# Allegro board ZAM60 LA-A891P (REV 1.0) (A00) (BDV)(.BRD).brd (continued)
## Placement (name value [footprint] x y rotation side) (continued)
RV507  100K_0402_5%  [R_0402]  282.19 68.44 270 top
RV508  1M_0402_5%  [R_0402]  201.96 84.25 0 bottom
RV509  1M_0402_5%  [R_0402]  199.62 82.97 180 top
RV510  4.7K_0402_5%  [R_0402]  235.06 79.62 270 top
RV511  4.7K_0402_5%  [R_0402]  234.17 78.71 90 top
RV514  100K_0402_5%  [R_0402]  232.09 86.22 270 top
RV515  100K_0402_5%  [R_0402]  232.99 84.43 180 top
RV516  2.2K_0402_5%  [R_0402]  199.5 69.27 270 top
RV517  2.2K_0402_5%  [R_0402]  202.83 69.25 90 bottom
RV518  2.2K_0402_5%  [R_0402]  201.23 85.41 270 top
RV519  2.2K_0402_5%  [R_0402]  202.13 85.41 270 top
RV600  4.99K_0402_1%  [R_0402]  222.76 73.77 270 bottom
RV601  4.7K_0402_5%  [R_0402]  235.53 73.57 180 top
RV602  4.7K_0402_5%  [R_0402]  222.43 75.16 0 bottom
RV603  4.7K_0402_5%  [R_0402]  232.55 75.35 180 top
RV604  100K_0402_5%  [R_0402]  220.47 67.59 90 top
RV605  100K_0402_5%  [R_0402]  219.38 70.27 0 top
RV606  1M_0402_5%  [R_0402]  227.64 69.39 270 bottom
RV607  1M_0402_5%  [R_0402]  223.64 69.46 270 bottom
RV608  100K_0402_5%  [R_0402]  219.57 69.38 0 top
RV609  100K_0402_5%  [R_0402]  220.28 72.06 270 top
RV610  4.7K_0402_5%  [R_0402]  228.09 72.86 90 bottom
RV611  4.7K_0402_5%  [R_0402]  234.5 68.67 90 top
RV612  4.7K_0402_5%  [R_0402]  237.17 68.67 90 top
RV613  4.7K_0402_5%  [R_0402]  237.17 71.61 270 top
RV614  4.7K_0402_5%  [R_0402]  234.5 71.61 270 top
RV615  4.7K_0402_5%  [R_0402]  235.53 74.46 180 top
RV616  4.7K_0402_5%  [R_0402]  227.2 73.77 270 bottom
RV617  4.7K_0402_5%  [R_0402]  235.39 69.58 270 top
RV618  4.7K_0402_5%  [R_0402]  236.28 69.58 270 top
RV619  4.7K_0402_5%  [R_0402]  236.28 70.7 90 top
RV620  4.7K_0402_5%  [R_0402]  235.39 70.7 90 top
RZ5  100K_0402_5%  [R_0402]  150.92 84.61 90 top
RZ8  2.2K_0402_5%  [R_0402]  252.56 13.27 270 top
RZ9  2.2K_0402_5%  [R_0402]  253.51 13.27 270 top
RZ10  1M_0402_5%  [R_0402]  258.94 12.83 270 top
RZ14  100K_0402_5%  [R_0402]  241.59 34.72 0 top
RZ15  100K_0402_5%  [R_0402]  244.34 34.72 180 top
RZ16  100K_0402_5%  [R_0402]  146.86 83.98 90 top
RZ17  0_0402_5%  [R0402_0OHM]  184.34 68.17 90 bottom
RZ18  4.7K_0402_5%  [R_0402]  247.32 22 90 top
RZ19  4.7K_0402_5%  [R_0402]  246.43 22 90 top
RZ21  33_0402_5%  [R_0402]  271.35 37.25 180 top
RZ22  10K_0402_5%  [R_0402]  268.81 34.71 180 top
RZ24  10K_0402_5%  [R_0402]  272.35 24.69 270 top
RZ25  390_0402_5%  [R_0402]  271.26 16.31 270 top
RZ26  33_0402_5%  [R_0402]  187.64 76.22 90 top
RZ27  110_0402_1%  [R_0402]  275.88 19.04 270 top
RZ28  330_0402_5%  [R_0402]  270.3 16.31 270 top
RZ29  33_0402_5%  [R_0402]  189.54 76.22 90 top
RZ30  33_0402_5%  [R_0402]  188.59 76.22 90 top
RZ31  100K_0402_5%  [R_0402]  286.88 80.05 0 top
RZ32  150_0402_5%  [R_0402]  289.61 82.46 0 top
RZ33  110_0402_1%  [R_0402]  283.72 79.04 270 top
RZ34  110_0402_1%  [R_0402]  285.62 82.4 180 top
RZ35  33_0402_5%  [R_0402]  187.89 79.49 270 top
RZ37  100K_0402_5%  [R_0402]  242.96 72.05 180 top
RZ38  100K_0402_5%  [R_0402]  251.2 30.46 180 top
RZ39  10K_0402_5%  [R_0402]  242.57 63.74 180 top
RZ40  100K_0402_5%  [R_0402]  244.22 56.67 90 top
RZ41  0_0402_5%  [R_0402]  200.95 47.23 270 top
RZ42  0_0402_5%  [R0402_0OHM]  201.86 47.23 270 top
RZ43  0_0402_5%  [R0402_0OHM]  243.84 72.92 270 top
RZ44  0.01_1206_1%  [R_1206]  200.02 41.22 270 top
RZ46  0_0603_5%  [R_0603]  220.33 61.94 180 top
RZ47  0_0402_5%  [R0402_0OHM]  220.84 64.31 180 top
RZ51  0_0402_5%  [R0402_0OHM]  267.01 33.79 90 top
RZ56  0_0402_5%  [R_0402]  252.69 24.75 0 top
RZ57  0_0402_5%  [R0402_0OHM]  252.69 25.65 0 top
SW1  SS3-CMFTQR9_3P  [SW_SS3-CMFTQR9_3P]  297.13 6.17 180 bottom
SW3  SKRBAAE010_4P  [SW_SKRBAAE010_4P]  294.16 86 270 top
T8  PAD~D  [TPC12]  169.05 48.09 0 top
T9  PAD~D  [TPC12]  253.6 32.78 90 top
T10  PAD~D  [TPC12]  128.53 70.99 180 bottom
T11  PAD~D  [TPC12]  127.01 70.48 180 bottom
T12  PAD~D  [TPC12]  135.21 77.65 0 top
T13  PAD~D  [TPC12]  127.87 72.39 180 bottom
T14  PAD~D  [TPC12]  133.77 77.99 0 top
T15  PAD~D  [TPC12]  133.07 76.77 0 top
T16  PAD~D  [TPC12]  173.73 60.24 0 top
T21  PAD~D  [TPC12]  177.24 61.06 180 bottom
T22  PAD~D  [TPC12]  174.2 62.45 0 top
T27  PAD~D  [TPC12]  173.86 57.7 180 bottom
T28  PAD~D  [TPC12]  128.78 47.15 180 bottom
T29  PAD~D  [TPC12]  127.16 47.45 180 bottom
T30  PAD~D  [TPC12]  128.7 77.99 180 bottom
T31  PAD~D  [TPC12]  129.78 78.75 180 bottom
T33  PAD~D  [TPC12]  140.46 78.33 180 bottom
T34  PAD~D  [TPC12]  142.3 78.33 180 bottom
T35  PAD~D  [TPC12]  130.03 65.94 180 bottom
T74  PAD~D  [TPC12]  129.45 64.5 180 bottom
T75  PAD~D  [TPC12]  126.48 65.18 180 bottom
T76  PAD~D  [TPC12]  137.32 77.98 0 top
T77  PAD~D  [TPC12]  132.45 78.45 0 top
T88  PAD~D  [TPC12]  261.22 86.41 180 top
T89  PAD~D  [TPC12]  261.24 87.86 180 top
T96  PAD~D  [TPC12]  259.93 58.29 180 top
T97  PAD~D  [TPC12]  252.03 73.65 180 top
T98  PAD~D  [TPC12]  258.02 72.16 180 top
T99  PAD~D  [TPC12]  252.11 72.17 0 top
T108  PAD~D  [TPC12]  213.17 76.03 0 top
T109  PAD~D  [TPC12]  167.71 78.56 0 top
TL1  NS692417  [MHPC_NS692417_24P]  279.42 81.51 180 bottom
UA1  -  [ALC3235-CG_MQFN48_6X6]  36.31 15.37 90 top
UC1  BDW-ULT-DDR3L_BGA1168  [BDW-ULT-DDR3L_BGA_1168P-T]  170.78 73.51 0 bottom
UC2  -  [W25Q64FVSSIQ_SO8]  190.61 68.5 0 bottom
UC3  -  [W25Q32FVSSIQ_SO8]  194.42 51.54 180 bottom
UC4  -  [74AHC1G09GW_TSSOP5]  185.23 72.82 180 top
UC5  TC7SH08FU_SSOP5~D  [TC7SH08FU_SSOP5]  187.74 70.85 0 top
UC6  TC7SH08FU_SSOP5~D  [TC7SH08FU_SSOP5]  186.5 52.57 270 top
UC7  -  [74CBTLV3126BQ_DHVQFN14_2P5X3]  90.03 59.31 270 bottom
UC8  -  [74AUP1G07GW_TSSOP5]  140.37 82.38 0 top
UD1  -  [74AUP1G07GW_TSSOP5]  146.15 19.79 0 top
UE1  ECE5048-LZY_DQFN132_11X11~D  [ECE5048-LZY_DQFN132_11X11]  258.62 70.96 180 top
UE2  -  [MEC5085-LZY_DQFN132_11X11]  262.69 47.91 180 top
UI1  SY6288D10CAC_MSOP8  [G547I2P81U_MSOP8]  91.7 84.21 270 bottom
UI2  SY6288D10CAC_MSOP8  [G547I2P81U_MSOP8]  255.09 92.9 270 bottom
UI3  -  [TPS2544RTER_WQFN16_3X3]  286.76 40.41 0 top
UI4  -  [PI3USB3102ZLEX_TQFN32_6X3]  181.18 96.08 0 top
UI5  -  [NX3DV221GM_XQFN10U10_2X1P55]  243.11 85.05 0 bottom
UL1  WGI218LM-QQ89-B0_QFN48_6X6~D  [WGI217LM-QPN9-A2_QFN48_6X6]  253.65 87.99 270 top
UL2  TC7SH08FU_SSOP5~D  [TC7SH08FU_SSOP5]  261.23 83.75 270 top
UL3  APE8990GN3B_SON14_2X3  [TPS22966DPUR_SON14_2X3]  248.79 28.88 90 top
UL4  PI3L720ZHEX_TQFN42_9X3P5~D  [PI3L720ZHEX_TQFN42_9X3P5]  268.46 73.5 0 top
UN1  LNG3DMTR_LGA16_3X3~D  [LNG3DMTR_LGA16_3X3]  279.73 8.26 270 bottom
UN2  -  [PI3EQX6741STZDEX_TQFN20_4X4]  265.04 19.67 180 top
UN3  TPS22967DSGR_SON8_2X2~D  [TPS22965DSGR_SON8_2X2]  249.91 18.45 270 top
UR1  OZ777FJ2LN-B1_QFN48_6X6  [OZ777FJ2LN_QFN48_6X6]  281.67 33.11 270 top
UV2  -  [AP2330W-7_SC59-3]  229.47 97.56 90 bottom
UV7  -  [PS8339BQFN56GTR2-A0_QFN56_7X7]  229.22 85.75 180 top
UV8  VMM3320BJGR_BGA168  [VMM3320BJGR_BGA_168P-NH]  203.01 72.64 90 top
UV9  W25X10CVSNIG_SO8  [W25X10BVSNIG_SO8]  200.83 74.52 270 bottom
UV10  APE8990GN3B_SON14_2X3  [TPS22966DPUR_SON14_2X3]  216.95 74.35 90 bottom
UV11  PI3C3125LEX_TSSOP14~D  [PI3C3125LEX_TSSOP14]  204.54 84.01 90 bottom
UV12  PI3C3125LEX_TSSOP14~D  [PI3C3125LEX_TSSOP14]  199.55 80.52 180 bottom
UV24  -  [AP2821KTR-G1_SOT23-5]  117.6 88.64 0 top
UV501  AP2337SA-7 SOT-23  [AP2330W-7_SC59-3]  282.83 64.24 90 top
UV502  PI3C3125LEX_TSSOP14~D  [PI3C3125LEX_TSSOP14]  286.35 64.77 180 bottom
UV600  -  [PS8338BQFN60GTR-A0_QFN60_5X9]  230.43 73.58 180 top
UZ1  AT97SC3205-X3A15-ABF_TSSOP28~D  [AT97SC3205_TSSOP28]  192.18 70.92 180 bottom
UZ2  APE8990GN3B_SON14_2X3  [TPS22966DPUR_SON14_2X3]  242.75 56.82 90 top
UZ5  -  [RT9818A-44GU3_SC70-3]  269.41 36.43 270 top
UZ6  TC7SH08FU_SSOP5~D  [TC7SH08FU_SSOP5]  268.26 33.68 270 top
UZ7  TPS22967DSGR_SON8_2X2~D  [TPS22965DSGR_SON8_2X2]  198.06 46.29 90 top
UZ8  APE8990GN3B_SON14_2X3  [TPS22966DPUR_SON14_2X3]  223.13 61.82 0 top
UZ9  APE8990GN3B_SON14_2X3  [TPS22966DPUR_SON14_2X3]  218.29 42.92 180 top
UZ10  TC7SH08FU_SSOP5~D  [TC7SH08FU_SSOP5]  264.03 58.72 180 top
UZ11  -  [TC7SH08FU_SSOP5]  249.72 26.95 270 top
YC1  32.768KHZ_12.5PF_9H03220008  [Y_9H03220008_2P]  184.16 48.61 270 bottom
YC2  24MHZ_12PF_X3G024000DC1H  [Y_X3G024000DC1H_4P]  156.21 82.32 180 bottom
YE1  32.768KHZ_12.5PF_Q13FC135000040  [Y_Q13FC135000040_2P]  269.35 44.39 90 top
YL1  25MHZ_18PF_7V25000034  [Y_7V25000034_4P]  249.31 80.66 90 top
YV2  27MHZ_12PF_X1E000021042600  [Y_X1E000021042600_4P]  215.16 68.78 0 top

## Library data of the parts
C33 PC5 PC10 PC21 PC22 PC101 PC102 PC200 PC201 PC205 PC303 PC305-PC308 PC401 PC404 PC515-PC518 PC704-PC709 PC714-PC717 PC723-PC725 PC807 PC900-PC904 PC913-PC917 = C_0805
C42 C43 C263 C294-C316 C319 CA1-CA6 CA8 CA11-CA13 CA17 CA19 CA22-CA24 CA27 CA28 CA30 CA33 CA35 CA41 CA45 CA47 CA50 CA54 CC1-CC15 CC17 CC20-CC22 CC24-CC28 CC35 CC37 CC40 CC43 CC44 CC49 CC50 CC52 CC57-CC59 CC61 CC65 CC66 CC68-CC73 CC78 CC80 CC82 CC83 CC94-CC97 CC100 CD1-CD11 CD21-CD27 CD30-CD44 CD54-CD60 CD63 CD64 CE2-CE6 CE8-CE20 CE22-CE30 CE34-CE40 CE44-CE46 CI3-CI5 CI7 CI10 CI12 CI13 CI16 CI17 CI19 CI27 CI28 CI38 CI414-CI419 CL1-CL3 CL5 CL6 CL8-CL11 CL13-CL15 CL18 CL19 CL23-CL27 CN2-CN4 CN13-CN20 CN23-CN26 CN29 CN30 CR2-CR4 CR6 CR8 CR10 CR13 CR15 CR17 CR19 CR21-CR27 CR31 CR35 CV1-CV6 CV10 CV11 CV23 CV26 CV60-CV62 CV66 CV69 CV71-CV80 CV83-CV86 CV88 CV89 CV91-CV93 CV95-CV100 CV102-CV111 CV113-CV123 CV145-CV150 CV152 CV153 CV156 CV157 CV374 CV501-CV510 CV512-CV514 CV600-CV613 CZ1 CZ2 CZ4-CZ7 CZ9 CZ13-CZ18 CZ20-CZ25 CZ30-CZ37 CZ39-CZ53 CZ55 CZ58 CZ59 CZ64-CZ67 PC3 PC4 PC20 PC105 PC106 PC203 PC206 PC212-PC215 PC300 PC304 PC311 PC400 PC402 PC403 PC501-PC504 PC506 PC511-PC514 PC520 PC521 PC702 PC703 PC711 PC713 PC718 PC719 PC726-PC728 PC732 PC737 PC741 PC805 PC809 PC810 PC817 = C_0402
C317 C318 CA9 CA10 CA16 CA18 CA25 CA26 CA29 CA31 CA43 CA44 CA46 CA48 CA49 CA51-CA53 CC23 CC29-CC34 CC36 CC47 CC51 CC55 CC56 CC60 CC63 CC64 CC79 CC84 CC85 CD12-CD19 CD28 CD29 CD45-CD52 CD61 CD62 CE1 CE7 CE21 CE31 CE32 CI6 CI11 CI420 CL4 CL7 CL12 CL16 CL17 CL20 CL21 CN1 CR1 CR7 CR9 CR14 CR18 CR34 CV9 CV12 CV27 CV82 CV87 CV90 CV94 CV101 CZ19 CZ38 CZ54 PC1 PC9 PC100 PC109-PC111 PC114 PC117-PC119 PC204 PC208 PC209 PC211 PC301 PC302 PC309 PC310 PC500 PC505 PC507-PC510 PC700 PC701 PC710 PC712 PC721 PC722 PC729 PC813 PC815 PC816 = C_0603
CC39 CD20 CD53 PC207 PC966 = C_D2
CC41 CC42 = C_D3
CC67 CC77 CC81 CI1 CI8 CI14 = C_1206
CL22 = C_1808
CMOS1 = SHORTPADS-S: User Part Number: PART#
CZ57 = C_B2
D19 DA4 DA5 DE1 DZ1-DZ6 = RB751S40T1G_SOD523-2
D20 = L30ESD24VC3-2_SOT23-3
DA1-DA3 DA6 DA7 = L03ESDL5V0CC3-2_SOT23-3
DI1 DI4 DI6 = L05ESDL5V0NA-4_SLP2510P8-10-9
DI2 DI3 DI5 DV4 PD5 = AZC199-02SPR7G_SOT23-3
DV1-DV3 PD815 PD817 = BAT54CW_SOT323-3
FD1-FD4 = FIDUCIAL_C40M80
H1-H4 H6 H7 H9-H11 H13 H21 = H_2P3
H5 = H_5P5N
H12 = H_3P6
H14-H17 = H_3P5
H18 = H_5P2X2P6N
H19 H20 = H_3P2
H22 = H_3P3
H23 = H_2P6N
JAPS1 = ACES_50506-01841-P01_18P
JDEG1 JLPDE1 = HB_A531015-SCHR21_10P
JDIMM1 JDIMM2 = LCN_DAN06-K4406-0103_204P
JDOCK1 = JAE_WD2F144WB5R400_144P
JEDP1 = ACES_50398-04041-001_40P
JFAN1 = ACES_50271-0040N-001_4P
JHDMI1 = CONCR_099BKAC19YBLCNF_19P-T
JHP1 = SINGA_2SJ3080-039111F_6P-T
JKBTP1 = E-T_6705K-Y16N-00L_16P
JLED1 = E-T_6705K-Y10N-00L_10P-T
JLOM1 = SANTA_130456-511_13P-T
JMDP1 = ACON_MAR2B-20K1803_20P-T
JNGFF1 = BELLW_80148-3221_67P-T
JNGFF2 = BELLW_80149-4221_67P-T
JRTC1 = TYCO_2-1775293-2_2P
JSATA1 = STARC_115B20-000000-G2-R_20P-T
JSD1 = T-SOL_156-2000302608_19P_NR-S
JSIM1 = T-SOL_159-1201300600_8P-T
JSPI1 = E-T_6700K-Y20N-00L_20P
JSPK1 = ACES_50279-0040N-001_4P
JTAG1 = SHORTPADS: User Part Number: PART#
JUSB1 JUSB2 = C-K_26210-8K1A-02_9P-T
JUSB3 = SINGA_2UB1641-000111F_9P-T
JUSH1 = E-T_6705K-Y20N-00L_20P
JXDP1 = SAMTE_BSH-030-01-L-D-A_60P
LA2 LA3 = MURAT_BLM15BD601SN1D_2P
LA5 = MURAT_BLM15PX600SN1D_2P
LA6-LA11 = MURAT_BLM15PX330SN1D_2P
LC1-LC5 = MURAT_LQM2MPN2R2NG0L_2P
LED3 = LED_LTW-193ZDS5_2P
LI1-LI9 LV3 LV6 LV10 LV12 LV27 LZ1 = MURAT_DLW21HN900HQ2L_4P
LL1 = TAIYO_BRC2012T4R7MD_2P
LV1 = MURAT_BLM15BB221SN1D_2P
LV22-LV25 = MURAT_BLM15PX181SN1D_2P
MIC1 = KNOW_SPM1437HM4H-6_6P
PBATT1 = DEREN_40-42251-01001RHF_10P-T
PC113 PC115 = C_APXK6R3ARA221MF451
PC519 = C_D
PD1 PD2 = TVNST52302AB0_SOT523-3
PD3 = BAS40-05W_SC70-3
PD4 = RB751V-40_SOD323-2
PD702 PD704 PD705 PD813 = SDMK0340L-7-F_SOD323-2
PD800 PD808 = PDS5100H-13_POWERDI5-3
PH500 PH501 PR1 PR2 PR7-PR15 PR17 PR18 PR100-PR102 PR104-PR107 PR114 PR201 PR205 PR206 PR209 PR303 PR306-PR310 PR315 PR400-PR403 PR500-PR516 PR518 PR521 PR523-PR525 PR527-PR529 PR535 PR703 PR706 PR707 PR710 PR711 PR713 PR715 PR722 PR725 PR729 PR737 PR738 PR740 PR745 PR788 PR799 PR810 PR813-PR816 PR818 PR819 PR822 PR826-PR830 PR844 PR846 PR858 PR863 PR864 PR874 R6 R41 R252-R268 R271-R273 RA1 RA2 RA5-RA9 RA12-RA14 RA17 RA18 RA21 RA24-RA32 RA38 RA40 RA44 RC1 RC2 RC7-RC11 RC14-RC23 RC25 RC27 RC29 RC31 RC33 RC34 RC38 RC55 RC61-RC63 RC66-RC70 RC72 RC74 RC78-RC82 RC91 RC92 RC95 RC98 RC99 RC102 RC103 RC106 RC109 RC112-RC133 RC136 RC139-RC142 RC149 RC152 RC153 RC155 RC156 RC158 RC160 RC163 RC164 RC171 RC174-RC176 RC178-RC180 RC183-RC195 RC197-RC199 RC201 RC202 RC204 RC207-RC209 RC211 RC213 RC216 RC218 RC224-RC231 RC240-RC243 RC245 RC247 RC300-RC306 RD2 RD4-RD7 RD9-RD14 RD18-RD25 RE5 RE8-RE12 RE17 RE20 RE21 RE24-RE27 RE31 RE33 RE35-RE37 RE42 RE43 RE48 RE51 RE55-RE58 RE60 RE62-RE75 RE77-RE79 RE81-RE84 RE86 RE88 RE274 RE276 RE277 RE280 RE281 RE283 RI13 RI14 RL1 RL2 RL4-RL6 RL9 RL11-RL20 RL29 RL30 RN1-RN14 RN16 RN18-RN25 RR1 RR2 RR5 RR6 RR8 RR11 RR15 RV1-RV9 RV50-RV52 RV54-RV58 RV60-RV68 RV73-RV91 RV100 RV210 RV212 RV501-RV505 RV507-RV511 RV514-RV519 RV600-RV620 RZ5 RZ8-RZ10 RZ14-RZ16 RZ18 RZ19 RZ21 RZ22 RZ24-RZ35 RZ37-RZ41 RZ56 = R_0402
PJP1 PJP18 PJP21 PJP22 PJP36 PJP100-PJP102 PJP203 PJP204 PJP300 = JUMP_43X118
PJP4 PJP5 PJP7 PJP10-PJP12 PJP14-PJP17 PJP20 PJP23-PJP25 PJP27-PJP29 PJP32 PJP35 PJP201 PJP202 PJP400 PJP401 PJP701 = JUMP_43X39
PJP6 PJP9 PJP13 PJP26 PJP200 PJP302 = JUMP_43X79
PJP500 PJP700 = JUMP_43X118-NPM
PJPDC1 = ACES_50290-0050N-001_5P-T
PL1 PL2 PL4 = TAIYO_FBMJ4516HS720NT_2P
PL3 = MURAT_BLM15AG102SN1D_2P
PL100 = L_5X5X3_M_2P-NPM
PL101 PL102 PL200 = PANAS_ETQP3W2R2WFN_2P
PL301 PL700 = L_5X5X3_M_2P
PL500 = PANAS_ETQP4LR15AFM_4P
PL501 = KC_FBMA-L11-453215800LMA90T_2P
PL701 = TOKO_FDVE1040-H-3R3M-P3_2P
PQ1 PQ829 = SI2301CDS-T1-GE3_SOT23-3
PQ2 = FDV301N-G_SOT23-3
PQ3 = MMST3904-7-F_SOT323-3
PQ4 PQ826 = FDMC6679AZ_MLP8-5
PQ6 = IMD2AT-108_SC74-6
PQ100 PQ101 PQ200 = SIS412DN-T1-GE3_POWERPAK8-5
PQ102 PQ103 PQ201 = SI7716ADN-T1-GE3_POWERPAK8-5
PQ700 PQ800 = SI4835DDY-T1-GE3_SO8
PQ701 PQ702 PQ814 = NTR4502PT1G_SOT23-3
PQ703 = NTGD4161PT1G_TSOP6
PQ705 = AON6970_DFN5X6D-8-7
PQ806 PQ813 PQ817 = DMN65D8LDW-7_SOT363-6
PQ810 PQ815 = FDS6679AZ-G_SO8
PQ816 PQ832 = DMN65D8LW-7_SOT323-3
PR6 PR103 PR108 PR113 PR207 PR210 PR313 PR520 PR531 PR532 PR534 PR536 PR539 PR700 PR702 PR704 PR705 PR709 PR714 PR716-PR718 PR720 PR728 PR743 PR811 PR812 PR842 PR843 PR845 PR848 PR850 PR851 PR853-PR855 PR857 PR859 PR895 RA35-RA37 RA45 RC4 RC26 RC35 RC50 RC65 RC77 RC87-RC89 RC161 RC212 RC217 RC219 RD15 RD16 RD27 RD28 RE32 RE61 RE275 RE279 RE282 RL3 RL7 RL10 RR3 RR4 RZ17 RZ42 RZ43 RZ47 RZ51 RZ57 = R0402_0OHM
PR16 PR835 = R_0805
PR109 PR110 PR200 PR202 PR517 PR519 PR526 PR712 PR723 PR831 PR832 PR838 PR847 PR860 RC196 RL21-RL28 RZ46 = R_0603
PR111 PR112 PR203 PR305 PR522 PR708 PR726 RZ44 = R_1206
PR204 PR312 RA3 RA4 RL8 = R0603_0OHM
PR701 PR721 = R_1206_4P-D
PRP2 RPC1-RPC12 RPC14-RPC20 RPE2-RPE10 RPV1 RPV2 = RP_0804_8P4R
PT1 PT2 T8-T16 T21 T22 T27-T31 T33-T35 T74-T77 T88 T89 T96-T99 T108 T109 = TPC12
PU1 = TS5A63157DCKR_SC70-6
PU100 = TPS51285BRUKR_QFN20_3X3
PU200 = RT8207MZQW_WQFN20_3X3
PU300 = SY8208DQNC_QFN10_3X3
PU400 = APL5930KAI-TRG_SO8
PU500 = TPS51622RSM_QFN32_4X4
PU501 = CSD97374CQ4M_SON8_3P5X4P5
PU700 = BQ24715URUYR_WQFN28_4X4
PU800 = CD3301RHHR_QFN36_6X6
PU804 PU806 UC5 UC6 UL2 UZ6 UZ10 UZ11 = TC7SH08FU_SSOP5
QA1 QD1 QV2 QV7 QV9 QV10 QV501 QV502 = L2N7002WT1G_SC-70-3
QA2 QA3 QC1 QE2 QL1 QL2 QN1 QV21 QZ2 QZ3 QZ7 QZ10 QZ11 = DMN66D0LDW-7_SOT363-6
QE3-QE7 = MMBT3904WT1G_SC70-3
QV1 = AO6405_TSOP6
QV8 QZ1 = LP2301ALT1G_SOT23-3
QV20 QZ6 = SI3456DDV-T1-GE3_TSOP6
QZ4 QZ9 = DDTA114EUA-7-F_SOT323-3
RA39 = R0805_0OHM
SW1 = SW_SS3-CMFTQR9_3P
SW3 = SW_SKRBAAE010_4P
TL1 = MHPC_NS692417_24P
UA1 = ALC3235-CG_MQFN48_6X6
UC1 = BDW-ULT-DDR3L_BGA_1168P-T
UC2 = W25Q64FVSSIQ_SO8
UC3 = W25Q32FVSSIQ_SO8
UC4 = 74AHC1G09GW_TSSOP5
UC7 = 74CBTLV3126BQ_DHVQFN14_2P5X3
UC8 UD1 = 74AUP1G07GW_TSSOP5
UE1 = ECE5048-LZY_DQFN132_11X11
UE2 = MEC5085-LZY_DQFN132_11X11
UI1 UI2 = G547I2P81U_MSOP8
UI3 = TPS2544RTER_WQFN16_3X3
UI4 = PI3USB3102ZLEX_TQFN32_6X3
UI5 = NX3DV221GM_XQFN10U10_2X1P55
UL1 = WGI217LM-QPN9-A2_QFN48_6X6
UL3 UV10 UZ2 UZ8 UZ9 = TPS22966DPUR_SON14_2X3
UL4 = PI3L720ZHEX_TQFN42_9X3P5
UN1 = LNG3DMTR_LGA16_3X3
UN2 = PI3EQX6741STZDEX_TQFN20_4X4
UN3 UZ7 = TPS22965DSGR_SON8_2X2
UR1 = OZ777FJ2LN_QFN48_6X6
UV2 UV501 = AP2330W-7_SC59-3
UV7 = PS8339BQFN56GTR2-A0_QFN56_7X7
UV8 = VMM3320BJGR_BGA_168P-NH
UV9 = W25X10BVSNIG_SO8
UV11 UV12 UV502 = PI3C3125LEX_TSSOP14
UV24 = AP2821KTR-G1_SOT23-5
UV600 = PS8338BQFN60GTR-A0_QFN60_5X9
UZ1 = AT97SC3205_TSSOP28
UZ5 = RT9818A-44GU3_SC70-3
YC1 = Y_9H03220008_2P
YC2 = Y_X3G024000DC1H_4P
YE1 = Y_Q13FC135000040_2P
YL1 = Y_7V25000034_4P
YV2 = Y_X1E000021042600_4P

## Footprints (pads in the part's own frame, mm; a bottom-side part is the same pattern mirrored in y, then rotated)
74AHC1G09GW_TSSOP5
  oval 0.381x1.346 smd: 1(0,0) 2(0.65,0) 3(1.3,0) 4(1.3,1.79) 5(0,1.79)
74AUP1G07GW_TSSOP5
  oval 0.381x1.346 smd: 1(0,0) 2(0.65,0) 3(1.3,0) 4(1.3,1.79) 5(0,1.79)
74CBTLV3126BQ_DHVQFN14_2P5X3
  oval 1.041x0.254 smd: 1(0,0) 7(2.95,0) 8(2.95,0.5) 14(0,0.5)
  oval 0.254x1.041 smd: 2(0.475,-0.975) 3(0.975,-0.975) 4(1.475,-0.975) 5(1.975,-0.975) 6(2.475,-0.975) 9(2.475,1.475) 10(1.975,1.475) 11(1.475,1.475) 12(0.975,1.475) 13(0.475,1.475)
  rect 1.499x0.991 smd: 15(1.475,0.25)
ACES_50271-0040N-001_4P
  oval 0.787x1.6 smd: 1(0,0) 2(-1.25,0) 3(-2.5,0) 4(-3.75,0)
  rect 2.108x2.997 smd: 5(2.55,-2.9) 6(-6.3,-2.9)
ACES_50279-0040N-001_4P
  oval 0.787x1.905 smd: 1(0,0) 2(1.25,0) 3(2.5,0) 4(3.75,0)
  rect 1.295x3.353 smd: 5(6.6,-4.925) 6(-2.85,-4.925)
ACES_50290-0050N-001_5P-T
  rect 0.838x7.01 smd: 1(0,0) 2(1.5,0) 3(3,0) 4(4.5,0) 5(6,0)
ACES_50398-04041-001_40P
  oval 0.254x1.295 smd: 1(0,0) 2(0.5,0) 3(1,0) 4(1.5,0) 5(2,0) 6(2.5,0) 7(3,0) 8(3.5,0) 9(4,0) 10(4.5,0) 11(5,0) 12(5.5,0) 13(6,0) 14(6.5,0) 15(7,0) 16(7.5,0) 17(8,0) 18(8.5,0) 19(9,0) 20(9.5,0) 21(10,0) 22(10.5,0) 23(11,0) 24(11.5,0) 25(12,0) 26(12.5,0) 27(13,0) 28(13.5,0) 29(14,0) 30(14.5,0) 31(15,0) 32(15.5,0) 33(16,0) 34(16.5,0) 35(17,0) 36(17.5,0) 37(18,0) 38(18.5,0) 39(19,0) 40(19.5,0)
  rect 1.194x3.2 smd: 41(-2.4,1.95) 45(21.9,1.95)
  rect 2.311x1.295 smd: 42(0.85,3.9) 43(9.75,3.9) 44(18.65,3.9)
ACES_50506-01841-P01_18P
  oval 0.305x0.889 smd: 1(0,0) 2(0.5,0) 3(1,0) 4(1.5,0) 5(2,0) 6(2.5,0) 7(3,0) 8(3.5,0) 9(4,0) 10(4.5,0) 11(5,0) 12(5.5,0) 13(6,0) 14(6.5,0) 15(7,0) 16(7.5,0) 17(8,0) 18(8.5,0)
  rect 0.991x2.007 smd: 19(-2.1,-3.05) 20(10.6,-3.05)
ACON_MAR2B-20K1803_20P-T
  round 0.991 hole 0.991 unplated: (-0.825,3.26) (6.825,3.26)
  oval 0.813x0.914 hole 0.61: 1(0,0) 3(0.5,1) 5(1.5,1) 7(2,0) 9(2.5,-1) 11(3.5,-1) 13(4,0) 15(4.5,1) 17(5.5,1) 19(6,0)
  oval 0.356x2.159 smd: 2(0.3,2.985) 4(0.9,2.985) 6(1.5,2.985) 8(2.1,2.985) 10(2.7,2.985) 12(3.3,2.985) 14(3.9,2.985) 16(4.5,2.985) 18(5.1,2.985) 20(5.7,2.985)
  oval 1.092x2.007 hole 0.711x1.6: 21(-2.1,1.66) 23(8.1,1.66)
  oval 1.092x1.803 hole 0.711x1.397: 22(-2.8,-3.04) 24(8.8,-3.04)
ALC3235-CG_MQFN48_6X6
  oval 0.203x0.889 smd: 1(0,0) 2(0.4,0) 3(0.8,0) 4(1.2,0) 5(1.6,0) 6(2,0) 7(2.4,0) 8(2.8,0) 9(3.2,0) 10(3.6,0) 11(4,0) 12(4.4,0) 25(4.4,6.1) 26(4,6.1) 27(3.6,6.1) 28(3.2,6.1) 29(2.8,6.1) 30(2.4,6.1) 31(2,6.1) 32(1.6,6.1) 33(1.2,6.1) 34(0.8,6.1) 35(0.4,6.1) 36(0,6.1)
  oval 0.889x0.203 smd: 13(5.25,0.85) 14(5.25,1.25) 15(5.25,1.65) 16(5.25,2.05) 17(5.25,2.45) 18(5.25,2.85) 19(5.25,3.25) 20(5.25,3.65) 21(5.25,4.05) 22(5.25,4.45) 23(5.25,4.85) 24(5.25,5.25) 37(-0.85,5.25) 38(-0.85,4.85) 39(-0.85,4.45) 40(-0.85,4.05) 41(-0.85,3.65) 42(-0.85,3.25) 43(-0.85,2.85) 44(-0.85,2.45) 45(-0.85,2.05) 46(-0.85,1.65) 47(-0.85,1.25) 48(-0.85,0.85)
  rect 4.394x4.394 smd: 49(2.2,3.05)
AO6405_TSOP6
  oval 0.508x1.473 smd: 1(0,0) 2(0.95,0) 3(1.9,0) 4(1.9,2.35) 5(0.95,2.35) 6(0,2.35)
AON6970_DFN5X6D-8-7
  oval 0.66x0.635 smd: 1(0,0) 3(3.81,5.67) 4(2.54,5.67) 5(1.27,5.67) 6(0,5.67)
  custom 0.485x0.485 smd: 2(1.905,0.655)
  rect 3.988x2.667 smd: 7(1.905,3.62)
AP2330W-7_SC59-3
  oval 0.787x0.991 smd: 1(0,0) 2(-0.95,-2.4) 3(0.95,-2.4)
AP2821KTR-G1_SOT23-5
  oval 0.508x0.787 smd: 1(0,0) 2(0.95,0) 3(1.9,0) 4(1.9,2.4) 5(0,2.4)
APL5930KAI-TRG_SO8
  oval 0.635x1.854 smd: 1(0,0) 2(1.27,0) 3(2.54,0) 4(3.81,0) 5(3.81,5.165) 6(2.54,5.165) 7(1.27,5.165) 8(0,5.165)
  rect 2.87x2.489 smd: 9(1.905,2.582)
AT97SC3205_TSSOP28
  oval 0.381x1.626 smd: 1(0,0) 2(0.65,0) 3(1.3,0) 4(1.95,0) 5(2.6,0) 6(3.25,0) 7(3.9,0) 8(4.55,0) 9(5.2,0) 10(5.85,0) 11(6.5,0) 12(7.15,0) 13(7.8,0) 14(8.45,0) 15(8.45,5.8) 16(7.8,5.8) 17(7.15,5.8) 18(6.5,5.8) 19(5.85,5.8) 20(5.2,5.8) 21(4.55,5.8) 22(3.9,5.8) 23(3.25,5.8) 24(2.6,5.8) 25(1.95,5.8) 26(1.3,5.8) 27(0.65,5.8) 28(0,5.8)
AZC199-02SPR7G_SOT23-3
  oval 1.016x1.524 smd: 1(0,0) 2(0.965,2.083) 3(-0.965,2.083)
BAS40-05W_SC70-3
  oval 0.508x0.559 smd: 1(0,0) 2(-0.65,-1.85) 3(0.65,-1.85)
BAT54CW_SOT323-3
  oval 0.61x0.559 smd: 1(0,0) 2(-0.65,-1.85) 3(0.65,-1.85)
BDW-ULT-DDR3L_BGA_1168P-T
  round 0.508 smd: A3(-1.137,0) A62(-38.036,0) AW1(0,22.042) AW63(-38.628,22.057) AY2(-0.543,22.628) AY62(-38.062,22.628) B2(-0.508,0.508) B63(-38.628,0.592) C1(0,1.137)
  round 0.381 smd: A4(-1.894,0) A5(-2.554,0) A6(-3.75,0) A59(-35.9,0) A60(-36.726,0) A61(-37.386,0) AA9(-5.032,11.576) AA21(-11.688,11.489) AA23(-13.115,11.489) AA58(-35.377,11.33) AB10(-5.476,12.053) AB20(-11.18,11.896) AB21(-11.688,12.302) AB22(-12.607,11.896) AB23(-13.115,12.302) AB57(-35.057,11.98) AC9(-5.032,12.529) AC20(-11.18,12.709) AC22(-12.607,12.709) AC58(-35.377,12.63) AD10(-5.476,13.005) AD21(-11.688,13.115) AD23(-13.115,13.115) AD57(-35.057,13.28) AE9(-5.032,13.481) AE10(-5.476,13.958) AE20(-11.18,13.521) AE21(-11.688,13.928) AE22(-12.607,13.521) AE23(-13.115,13.928) AE58(-35.377,13.931) AF9(-5.032,14.434) AF11(-6.059,14.282) AF12(-6.872,14.282) AF14(-7.685,14.282) AF15(-8.497,14.282) AF17(-9.31,14.282) AF18(-10.123,14.282) AF20(-10.936,14.282) AF22(-12.607,14.334) AG10(-5.653,14.79) AG11(-6.465,14.79) AG13(-7.278,14.79) AG14(-8.091,14.79) AG16(-8.904,14.79) AG17(-9.717,14.79) AG19(-10.529,14.79) AG20(-11.342,14.79) AG23(-13.115,14.741) AG57(-35.057,14.581) AG58(-35.692,15.009) AH22(-12.607,15.147) AH24(-13.92,15.289) AH26(-15.22,15.289) AH28(-16.521,15.289) AH30(-17.821,15.289) AH32(-19.122,15.289) AH34(-20.422,15.289) AH36(-21.723,15.289) AH38(-23.023,15.289) AH40(-24.324,15.289) AH42(-25.624,15.289) AH44(-26.925,15.289) AH46(-28.225,15.289) AH49(-29.526,15.289) AH51(-30.826,15.289) AH53(-32.127,15.289) AH55(-33.427,15.289) AH57(-34.728,15.289) AJ23(-13.115,15.553) AJ25(-14.57,15.614) AJ27(-15.871,15.614) AJ29(-17.171,15.614) AJ31(-18.472,15.614) AJ33(-19.772,15.614) AJ35(-21.073,15.614) AJ37(-22.373,15.614) AJ39(-23.674,15.614) AJ41(-24.974,15.614) AJ43(-26.275,15.614) AJ45(-27.575,15.614) AJ47(-28.875,15.614) AJ50(-30.176,15.614) AJ52(-31.476,15.614) AJ54(-32.777,15.614) AJ56(-34.077,15.614) AJ58(-35.378,15.614) AT1(0,19.997) AT63(-38.628,19.848) AU1(0,20.657) AU63(-38.628,20.673) AV1(0,21.318) AV2(-0.66,21.308) AV62(-37.978,21.318) AV63(-38.628,21.333) AW2(-0.66,21.968) AW3(-1.321,21.968) AW61(-37.328,21.978) AW62(-37.978,21.978) AY3(-1.267,22.628) AY4(-1.928,22.628) AY5(-2.588,22.628) AY59(-36.088,22.628) AY60(-36.748,22.628) AY61(-37.409,22.628) B3(-1.259,0.65) B61(-37.315,0.66) B62(-37.978,0.724) C2(-0.65,1.259) C62(-37.978,1.384) C63(-38.628,1.316) D1(0,1.861) D63(-38.628,1.976) E1(0,2.522) E23(-13.333,2.601) E25(-14.714,2.601) E27(-15.84,2.601) E29(-17.221,2.601) E31(-18.348,2.601) E33(-19.729,2.601) E35(-20.855,2.601) E37(-22.236,2.601) E39(-23.363,2.601) E41(-24.744,2.601) E43(-25.87,2.601) E45(-27.251,2.601) E47(-28.378,2.601) E49(-29.759,2.601) E51(-30.885,2.601) E53(-32.266,2.601) E55(-33.393,2.601) E57(-34.774,2.601) E63(-38.628,2.647) F1(0,3.436) F22(-12.717,3.058) F24(-14.023,3.126) F26(-15.277,3.126) F28(-16.531,3.126) F30(-17.785,3.126) F32(-19.038,3.126) F34(-20.292,3.126) F36(-21.546,3.126) F38(-22.8,3.126) F40(-24.053,3.126) F42(-25.307,3.126) F44(-26.561,3.126) F46(-27.815,3.126) F48(-29.068,3.126) F50(-30.322,3.126) F52(-31.576,3.126) F54(-32.83,3.126) F56(-34.083,3.126) F58(-35.377,3.126) G22(-12.607,3.768) G23(-13.333,3.451) G25(-14.714,3.451) G27(-15.84,3.451) G29(-17.221,3.451) G31(-18.348,3.451) G33(-19.729,3.451) G35(-20.855,3.451) G37(-22.236,3.451) G39(-23.363,3.451) G41(-24.744,3.451) G43(-25.87,3.451) G45(-27.251,3.451) G47(-28.378,3.451) G49(-29.759,3.451) G51(-30.885,3.451) G53(-32.266,3.451) G55(-33.393,3.451) G57(-34.774,3.451) H22(-12.607,4.581) H23(-13.115,4.174) H57(-35.057,4.101) J22(-12.607,5.393) J23(-13.115,4.987) J58(-35.377,4.827) K9(-5.032,5.861) K10(-5.935,5.7) K12(-6.888,5.7) K14(-7.84,5.7) K16(-8.793,5.7) K18(-9.745,5.7) K19(-10.698,5.7) K21(-11.65,5.7) K23(-13.115,5.8) K57(-35.057,5.478) L10(-5.476,6.338) L11(-6.412,6.144) L13(-7.364,6.144) L15(-8.317,6.144) L17(-9.269,6.144) L18(-10.222,6.144) L20(-11.18,6.206) L22(-12.607,6.206) L58(-35.377,6.128) M9(-5.032,6.814) M20(-11.18,7.019) M21(-11.688,6.613) M22(-12.607,7.019) M23(-13.115,6.613) M57(-35.057,6.778) N10(-5.476,7.29) N21(-11.688,7.425) N23(-13.115,7.425) N58(-35.377,7.428) P9(-5.032,7.766) P20(-11.18,7.832) P22(-12.607,7.832) P57(-35.057,8.078) R10(-5.476,8.243) R20(-11.18,8.645) R21(-11.688,8.238) R22(-12.607,8.645) R23(-13.115,8.238) T9(-5.032,8.719) T21(-11.688,9.051) T23(-13.115,9.051) T58(-35.377,8.729) U9(-5.032,9.671) U10(-5.476,9.195) U20(-11.18,9.457) U22(-12.607,9.457) U57(-35.057,9.379) V10(-5.476,10.148) V21(-11.688,9.864) V23(-13.115,9.864) V58(-35.377,10.029) W9(-5.032,10.624) W20(-11.18,10.27) W21(-11.688,10.677) W22(-12.607,10.27) W23(-13.115,10.677) W57(-35.057,10.679) Y10(-5.476,11.1) Y20(-11.18,11.083) Y22(-12.607,11.083)
  round 0.305 smd: A8(-4.538,0) A9(-5.452,0) A11(-6.367,0) A12(-7.116,0) A14(-8.03,0) A15(-8.945,0) A17(-9.694,0) A18(-10.608,0) A20(-11.523,0) A21(-12.272,0) A23(-13.186,0) A24(-14.023,0.325) A25(-14.714,0) A27(-15.84,0) A28(-16.531,0.325) A29(-17.221,0) A31(-18.348,0) A32(-19.038,0.325) A33(-19.729,0) A35(-20.855,0) A36(-21.546,0.325) A37(-22.236,0) A39(-23.363,0) A40(-24.053,0.325) A41(-24.744,0) A43(-25.87,0) A44(-26.561,0.325) A45(-27.251,0) A47(-28.378,0) A48(-29.068,0.325) A49(-29.759,0) A51(-30.885,0) A52(-31.576,0.325) A53(-32.266,0) A55(-33.393,0) A56(-34.083,0.325) A57(-34.774,0) AA1(0,11.717) AA2(-0.65,11.717) AA3(-1.3,11.678) AA4(-1.951,11.678) AA59(-36.027,11.638) AA60(-36.678,11.638) AA61(-37.328,11.638) AA62(-37.978,11.676) AA63(-38.628,11.676) AB5(-2.637,12.053) AB6(-3.287,12.053) AB7(-3.937,12.053) AB8(-4.587,12.053) AC1(0,12.466) AC2(-0.65,12.466) AC3(-1.3,12.504) AC4(-1.951,12.504) AC59(-36.027,12.464) AC60(-36.678,12.464) AC61(-37.328,12.464) AC62(-37.978,12.426) AC63(-38.628,12.426) AD1(0,13.215) AD2(-0.65,13.215) AD3(-1.3,13.177) AD4(-1.951,13.177) AD5(-2.637,13.005) AD6(-3.287,13.005) AD7(-3.937,13.005) AD8(-4.587,13.005) AD59(-36.027,13.137) AD60(-36.678,13.137) AD61(-37.328,13.137) AD62(-37.978,13.175) AD63(-38.628,13.175) AE5(-2.637,13.958) AE6(-3.287,13.958) AE7(-3.937,13.958) AE8(-4.587,13.958) AE59(-36.027,13.962) AE60(-36.678,13.962) AE61(-37.328,13.962) AE62(-37.978,13.924) AE63(-38.628,13.924) AF1(0,13.964) AF2(-0.65,13.964) AF3(-1.3,14.003) AF4(-1.951,14.003) AG1(0,14.714) AG2(-0.65,14.714) AG3(-1.3,14.676) AG4(-1.951,14.676) AG5(-2.637,14.91) AG6(-3.287,14.91) AG7(-3.937,14.91) AG8(-4.587,14.91) AG21(-11.955,15.122) AG60(-36.352,14.602) AG61(-37.003,14.602) AG62(-37.653,14.602) AG63(-38.303,14.602) AH1(0,15.463) AH2(-0.65,15.463) AH3(-1.3,15.501) AH4(-1.951,15.501) AH10(-5.653,15.476) AH11(-6.465,15.476) AH13(-7.278,15.476) AH14(-8.091,15.476) AH16(-8.904,15.476) AH17(-9.717,15.476) AH19(-10.529,15.476) AH20(-11.342,15.476) AH60(-36.678,15.278) AH61(-37.328,15.278) AH62(-37.978,15.278) AH63(-38.628,15.278) AJ5(-2.637,15.863) AJ6(-3.287,15.863) AJ7(-3.937,15.863) AJ8(-4.587,15.863) AJ10(-5.653,16.126) AJ11(-6.465,16.126) AJ13(-7.278,16.126) AJ14(-8.091,16.126) AJ60(-36.352,15.954) AJ61(-37.003,15.954) AJ62(-37.653,15.954) AJ63(-38.303,15.954) AK1(0,16.212) AK2(-0.65,16.212) AK3(-1.3,16.174) AK4(-1.951,16.174) AK8(-4.303,16.451) AK18(-9.848,16.266) AK20(-10.801,16.266) AK21(-11.753,16.266) AK60(-36.678,16.523) AK61(-37.328,16.523) AK62(-37.978,16.629) AK63(-38.628,16.629) AL1(0,16.962) AL2(-0.65,16.962) AL3(-1.3,17) AL4(-1.951,17) AL5(-2.901,16.776) AL7(-3.739,16.776) AL8(-4.303,17.101) AL10(-5.658,16.776) AL11(-6.221,17.101) AL13(-7.576,16.776) AL15(-8.14,17.101) AL17(-9.222,16.583) AL18(-9.848,16.916) AL20(-10.801,16.916) AL21(-11.753,16.916) AL22(-12.706,16.916) AL23(-13.529,16.916) AL25(-14.504,16.916) AL26(-15.456,16.916) AL28(-16.409,16.916) AL29(-17.361,16.916) AL31(-18.26,16.591) AL32(-18.824,16.916) AL33(-19.726,16.916) AL35(-20.729,16.916) AL36(-21.58,16.916) AL38(-22.634,16.916) AL39(-23.542,16.591) AL40(-24.131,16.916) AL42(-24.944,16.916) AL43(-25.897,16.916) AL45(-26.874,16.916) AL46(-27.802,16.916) AL48(-28.856,16.916) AL49(-29.757,16.916) AL51(-30.761,16.916) AL52(-31.583,16.916) AL54(-32.61,16.916) AL55(-33.562,16.916) AL57(-34.509,16.916) AL58(-35.408,16.916) AL60(-36.352,17.169) AL61(-37.003,17.169) AM1(0,17.711) AM2(-0.65,17.711) AM3(-1.3,17.673) AM4(-1.951,17.673) AM5(-2.901,17.426) AM7(-3.739,17.426) AM8(-4.303,17.752) AM10(-5.658,17.426) AM11(-6.221,17.752) AM13(-7.576,17.426) AM15(-8.14,17.752) AM17(-9.222,17.233) AM18(-9.848,17.567) AM20(-10.801,17.567) AM21(-11.753,17.567) AM22(-12.706,17.567) AM23(-13.529,17.567) AM25(-14.504,17.567) AM26(-15.456,17.567) AM28(-16.409,17.567) AM29(-17.361,17.567) AM31(-18.26,17.242) AM32(-18.824,17.567) AM33(-19.726,17.567) AM35(-20.729,17.567) AM36(-21.58,17.567) AM38(-22.634,17.567) AM40(-24.131,17.567) AM42(-24.944,17.567) AM43(-25.897,17.567) AM45(-26.874,17.567) AM46(-27.802,17.567) AM48(-28.856,17.567) AM49(-29.757,17.567) AM51(-30.761,17.567) AM52(-31.583,17.567) AM54(-32.61,17.567) AM55(-33.562,17.567) AM57(-34.509,17.567) AM58(-35.408,17.567) AM60(-36.678,17.816) AM61(-37.328,17.816) AM62(-37.978,17.709) AM63(-38.628,17.709) AN1(0,18.46) AN2(-0.65,18.46) AN3(-1.3,18.498) AN4(-1.951,18.498) AN5(-2.901,18.077) AN7(-3.739,18.077) AN8(-4.303,18.402) AN10(-5.658,18.077) AN11(-6.221,18.402) AN13(-7.576,18.077) AN15(-8.14,18.402) AN17(-9.222,17.883) AN18(-9.848,18.217) AN20(-10.801,18.217) AN21(-11.753,18.217) AN22(-12.706,18.217) AN23(-13.529,18.217) AN25(-14.504,18.217) AN26(-15.456,18.217) AN28(-16.409,18.217) AN29(-17.361,18.217) AN31(-18.26,17.892) AN32(-18.824,18.217) AN33(-19.726,18.217) AN35(-20.729,18.217) AN36(-21.58,18.217) AN38(-22.634,18.217) AN39(-23.542,17.892) AN40(-24.131,18.217) AN42(-24.944,18.217) AN43(-25.897,18.217) AN45(-26.874,18.217) AN46(-27.802,18.217) AN48(-28.856,18.217) AN49(-29.757,18.217) AN51(-30.761,18.217) AN52(-31.583,18.217) AN54(-32.61,18.217) AN55(-33.562,18.217) AN57(-34.509,18.217) AN58(-35.408,18.217) AN60(-36.352,18.385) AN61(-37.003,18.385) AN62(-37.653,18.385) AN63(-38.303,18.385) AP1(0,19.21) AP2(-0.65,19.21) AP3(-1.3,19.171) AP4(-1.951,19.171) AP5(-2.901,18.727) AP7(-3.739,18.727) AP8(-4.303,19.052) AP10(-5.658,18.727) AP11(-6.221,19.052) AP13(-7.576,18.727) AP15(-8.14,19.052) AP17(-9.222,18.533) AP18(-9.848,18.867) AP20(-10.801,18.867) AP21(-11.753,18.867) AP22(-12.706,18.867) AP23(-13.529,18.867) AP25(-14.504,18.867) AP26(-15.456,18.867) AP28(-16.409,18.867) AP29(-17.361,18.867) AP31(-18.26,18.542) AP32(-18.824,18.867) AP33(-19.726,18.867) AP35(-20.729,18.867) AP36(-21.58,18.867) AP38(-22.634,18.867) AP39(-23.542,18.542) AP40(-24.131,18.867) AP42(-24.944,18.867) AP43(-25.897,18.867) AP45(-26.874,18.867) AP46(-27.802,18.867) AP48(-28.856,18.867) AP49(-29.757,18.867) AP51(-30.761,18.867) AP52(-31.583,18.867) AP54(-32.61,18.867) AP55(-33.562,18.867) AP57(-34.509,18.867) AP58(-35.408,18.867) AP60(-36.678,19.06) AP61(-37.328,19.06) AP62(-37.978,19.06) AP63(-38.628,19.06) AR5(-2.901,19.377) AR7(-3.739,19.377) AR8(-4.303,19.702) AR10(-5.658,19.377) AR11(-6.221,19.702) AR13(-7.576,19.377) AR15(-8.14,19.702) AR17(-9.222,19.184) AR18(-9.848,19.517) AR20(-10.801,19.517) AR21(-11.753,19.517) AR22(-12.706,19.517) AR23(-13.529,19.517) AR25(-14.504,19.517) AR26(-15.456,19.517) AR28(-16.409,19.517) AR29(-17.361,19.517) AR31(-18.26,19.192) AR32(-18.824,19.517) AR33(-19.726,19.517) AR35(-20.729,19.517) AR36(-21.58,19.517) AR38(-22.634,19.517) AR39(-23.542,19.192) AR40(-24.131,19.517) AR42(-24.944,19.517) AR43(-25.897,19.517) AR45(-26.874,19.517) AR46(-27.802,19.517) AR48(-28.856,19.517) AR49(-29.757,19.517) AR51(-30.761,19.517) AR52(-31.583,19.517) AR54(-32.61,19.517) AR55(-33.562,19.517) AR57(-34.509,19.517) AR58(-35.408,19.517) AT2(-0.65,19.959) AT3(-1.3,19.997) AT4(-1.951,19.997) AT5(-2.901,20.027) AT7(-3.739,20.027) AT10(-5.658,20.027) AT13(-7.576,20.027) AT35(-20.437,20.22) AT37(-22.011,20.22) AT40(-23.586,20.22) AT42(-25.161,20.22) AT43(-26.736,20.22) AT46(-28.311,20.22) AT49(-29.912,20.248) AT61(-37.003,19.634) AT62(-37.812,19.69) AU2(-0.655,20.647) AU3(-1.315,20.647) AU4(-1.976,20.647) AU6(-3.337,20.678) AU7(-4.163,20.678) AU8(-4.836,20.678) AU10(-5.661,20.678) AU11(-6.335,20.678) AU12(-7.16,20.678) AU14(-7.833,20.678) AU15(-8.659,20.678) AU16(-9.222,20.353) AU17(-9.86,20.678) AU18(-10.536,20.353) AU19(-11.105,20.678) AU20(-11.751,20.353) AU21(-12.397,20.678) AU22(-12.966,20.353) AU23(-13.642,20.678) AU24(-14.318,20.353) AU25(-14.993,20.678) AU26(-15.669,20.353) AU27(-16.238,20.678) AU28(-16.884,20.353) AU29(-17.531,20.678) AU30(-18.1,20.353) AU31(-18.775,20.678) AU33(-19.372,20.33) AU34(-19.974,20.678) AU35(-20.899,20.678) AU36(-21.549,20.678) AU37(-22.474,20.678) AU39(-23.124,20.678) AU40(-24.048,20.678) AU41(-24.699,20.678) AU42(-25.623,20.678) AU43(-26.274,20.678) AU44(-27.198,20.678) AU46(-27.848,20.678) AU47(-28.773,20.678) AU49(-29.423,20.678) AU50(-30.4,20.678) AU51(-30.98,20.353) AU52(-31.656,20.678) AU53(-32.331,20.353) AU54(-32.9,20.678) AU55(-33.547,20.353) AU56(-34.193,20.678) AU57(-34.762,20.353) AU58(-35.438,20.678) AU59(-36.002,20.353) AU60(-36.566,20.678) AU61(-37.277,20.401) AU62(-37.978,20.663) AV3(-1.321,21.308) AV4(-1.976,21.308) AV5(-2.664,21.328) AV6(-3.337,21.328) AV7(-4.163,21.328) AV8(-4.836,21.328) AV10(-5.661,21.328) AV11(-6.335,21.328) AV12(-7.16,21.328) AV14(-7.833,21.328) AV15(-8.659,21.328) AV16(-9.222,21.003) AV17(-9.86,21.328) AV18(-10.536,21.003) AV19(-11.105,21.328) AV20(-11.751,21.003) AV21(-12.397,21.328) AV22(-12.966,21.003) AV23(-13.642,21.328) AV24(-14.318,21.003) AV25(-14.993,21.328) AV26(-15.669,21.003) AV27(-16.238,21.328) AV28(-16.884,21.003) AV29(-17.531,21.328) AV30(-18.1,21.003) AV31(-18.775,21.328) AV33(-19.4,21.003) AV34(-20.024,21.328) AV35(-20.849,21.328) AV36(-21.599,21.328) AV37(-22.424,21.328) AV39(-23.173,21.328) AV40(-23.999,21.328) AV41(-24.748,21.328) AV42(-25.574,21.328) AV43(-26.323,21.328) AV44(-27.149,21.328) AV46(-27.898,21.328) AV47(-28.723,21.328) AV49(-29.473,21.328) AV50(-30.298,21.328) AV51(-30.98,21.003) AV52(-31.656,21.328) AV53(-32.331,21.003) AV54(-32.9,21.328) AV55(-33.547,21.003) AV56(-34.193,21.328) AV57(-34.762,21.003) AV58(-35.438,21.328) AV59(-36.002,21.003) AV60(-36.566,21.328) AV61(-37.302,21.051) AW4(-1.976,21.968) AW5(-2.626,21.978) AW6(-3.375,21.978) AW7(-4.125,21.978) AW8(-4.874,21.978) AW10(-5.623,21.978) AW11(-6.373,21.978) AW12(-7.122,21.978) AW14(-7.871,21.978) AW15(-8.621,21.978) AW16(-9.222,21.653) AW17(-9.86,21.978) AW18(-10.536,21.653) AW19(-11.211,21.978) AW21(-12.291,21.978) AW22(-12.966,21.653) AW23(-13.642,21.978) AW24(-14.318,21.653) AW25(-14.993,21.978) AW26(-15.669,21.653) AW27(-16.345,21.978) AW29(-17.424,21.978) AW30(-18.1,21.653) AW31(-18.775,21.978) AW33(-19.451,21.653) AW34(-20.024,21.978) AW35(-20.849,21.978) AW36(-21.599,21.978) AW37(-22.424,21.978) AW39(-23.173,21.978) AW40(-23.999,21.978) AW41(-24.748,21.978) AW42(-25.574,21.978) AW43(-26.323,21.978) AW44(-27.149,21.978) AW46(-27.898,21.978) AW47(-28.723,21.978) AW49(-29.473,21.978) AW50(-30.298,21.978) AW51(-30.98,21.653) AW52(-31.656,21.978) AW53(-32.331,21.653) AW54(-33.007,21.978) AW56(-34.087,21.978) AW57(-34.762,21.653) AW58(-35.438,21.978) AW59(-36.002,21.653) AW60(-36.566,21.978) AY6(-3.375,22.628) AY7(-4.125,22.628) AY8(-4.874,22.628) AY10(-5.623,22.628) AY11(-6.373,22.628) AY12(-7.122,22.628) AY14(-7.871,22.628) AY15(-8.621,22.628) AY16(-9.184,22.303) AY17(-9.86,22.628) AY18(-10.536,22.303) AY19(-11.211,22.628) AY21(-12.291,22.628) AY22(-12.966,22.303) AY23(-13.642,22.628) AY24(-14.318,22.303) AY25(-14.993,22.628) AY26(-15.669,22.303) AY27(-16.345,22.628) AY29(-17.424,22.628) AY30(-18.1,22.303) AY31(-18.775,22.628) AY33(-19.451,22.303) AY34(-20.024,22.628) AY35(-20.849,22.628) AY36(-21.599,22.628) AY37(-22.424,22.628) AY39(-23.173,22.628) AY40(-23.999,22.628) AY41(-24.748,22.628) AY42(-25.574,22.628) AY43(-26.323,22.628) AY44(-27.149,22.628) AY46(-27.898,22.628) AY47(-28.723,22.628) AY49(-29.473,22.628) AY50(-30.298,22.628) AY51(-30.98,22.303) AY52(-31.656,22.628) AY53(-32.331,22.303) AY54(-33.007,22.628) AY56(-34.087,22.628) AY57(-34.762,22.303) AY58(-35.438,22.628) B4(-1.922,0.65) B5(-3.138,0.643) B6(-4.119,0.643) B8(-4.891,0.643) B9(-5.716,0.643) B11(-6.697,0.643) B12(-7.469,0.643) B14(-8.294,0.643) B15(-9.275,0.643) B17(-10.047,0.643) B18(-10.872,0.643) B20(-11.853,0.643) B21(-12.272,1.196) B22(-12.625,0.643) B23(-13.451,0.643) B24(-14.023,0.975) B25(-14.714,0.65) B26(-15.277,0.975) B27(-15.84,0.65) B28(-16.531,0.975) B29(-17.221,0.65) B30(-17.785,0.975) B31(-18.348,0.65) B32(-19.038,0.975) B33(-19.729,0.65) B34(-20.292,0.975) B35(-20.855,0.65) B36(-21.546,0.975) B37(-22.236,0.65) B38(-22.8,0.975) B39(-23.363,0.65) B40(-24.053,0.975) B41(-24.744,0.65) B42(-25.307,0.975) B43(-25.87,0.65) B44(-26.561,0.975) B45(-27.251,0.65) B46(-27.815,0.975) B47(-28.378,0.65) B48(-29.068,0.975) B49(-29.759,0.65) B50(-30.322,0.975) B51(-30.885,0.65) B52(-31.576,0.975) B53(-32.266,0.65) B54(-32.83,0.975) B55(-33.393,0.65) B56(-34.083,0.975) B57(-34.774,0.65) B58(-35.337,0.975) B59(-35.9,0.65) B60(-36.665,0.66) C3(-1.302,1.302) C4(-2.118,1.272) C5(-2.772,1.196) C6(-3.776,1.196) C8(-4.538,1.196) C9(-5.351,1.196) C11(-6.354,1.196) C12(-7.116,1.196) C14(-7.929,1.196) C15(-8.932,1.196) C17(-9.694,1.196) C18(-10.507,1.196) C20(-11.51,1.196) C21(-11.891,1.786) C22(-12.678,1.786) C23(-13.085,1.196) C24(-14.051,2.032) C25(-14.714,1.3) C26(-15.277,1.626) C27(-15.84,1.3) C28(-16.558,2.032) C29(-17.221,1.3) C30(-17.785,1.626) C31(-18.348,1.3) C32(-19.066,2.032) C33(-19.729,1.3) C34(-20.292,1.626) C35(-20.855,1.3) C36(-21.573,2.032) C37(-22.236,1.3) C38(-22.8,1.626) C39(-23.363,1.3) C40(-24.081,2.032) C41(-24.744,1.3) C42(-25.307,1.626) C43(-25.87,1.3) C44(-26.588,2.032) C45(-27.251,1.3) C46(-27.815,1.626) C47(-28.378,1.3) C48(-29.07,2.032) C49(-29.759,1.3) C50(-30.322,1.626) C51(-30.885,1.3) C52(-31.578,1.991) C53(-32.266,1.3) C54(-32.83,1.626) C55(-33.393,1.3) C56(-34.085,1.991) C57(-34.774,1.3) C58(-35.337,1.626) C59(-35.9,1.3) C61(-37.003,1.237) D2(-0.65,2.075) D3(-1.3,2.037) D5(-2.678,1.842) D6(-3.369,1.786) D8(-4.157,1.786) D9(-4.944,1.786) D11(-5.852,1.786) D12(-6.735,1.786) D14(-7.522,1.786) D15(-8.43,1.786) D17(-9.313,1.786) D18(-10.1,1.786) D20(-11.008,1.786) D21(-12.235,2.423) D23(-13.377,1.786) D25(-14.714,1.951) D26(-15.277,2.276) D27(-15.84,1.951) D29(-17.221,1.951) D30(-17.785,2.276) D31(-18.348,1.951) D33(-19.729,1.951) D34(-20.292,2.276) D35(-20.855,1.951) D37(-22.236,1.951) D38(-22.8,2.276) D39(-23.363,1.951) D41(-24.744,1.951) D42(-25.307,2.276) D43(-25.87,1.951) D45(-27.251,1.951) D46(-27.815,2.276) D47(-28.378,1.951) D49(-29.759,1.951) D50(-30.322,2.276) D51(-30.885,1.951) D53(-32.266,1.951) D54(-32.83,2.276) D55(-33.393,1.951) D57(-34.774,1.951) D58(-35.337,2.276) D59(-35.9,1.951) D60(-36.678,1.801) D61(-37.328,1.801) D62(-37.978,2.035) E2(-0.65,2.725) E3(-1.3,2.687) E4(-1.951,2.687) E5(-2.602,2.619) E6(-3.554,2.619) E8(-4.507,2.619) E10(-5.459,2.619) E11(-6.412,2.619) E13(-7.364,2.619) E15(-8.317,2.619) E17(-9.269,2.619) E18(-10.222,2.619) E20(-11.174,2.619) E59(-36.027,2.647) E60(-36.678,2.647) E61(-37.328,2.647) E62(-37.978,2.685) F2(-0.65,3.474) F3(-1.3,3.512) F4(-1.951,3.512) F5(-2.602,3.269) F6(-3.554,3.269) F8(-4.507,3.269) F10(-5.459,3.269) F11(-6.412,3.269) F13(-7.364,3.269) F15(-8.317,3.269) F17(-9.269,3.269) F18(-10.222,3.269) F20(-11.174,3.269) F59(-36.027,3.472) F60(-36.678,3.472) F61(-37.328,3.472) F62(-37.978,3.434) F63(-38.628,3.434) G1(0,4.224) G2(-0.65,4.224) G3(-1.3,4.185) G4(-1.951,4.185) G5(-2.602,3.919) G6(-3.554,3.919) G8(-4.507,3.919) G10(-5.459,3.919) G11(-6.412,3.919) G13(-7.364,3.919) G15(-8.317,3.919) G17(-9.269,3.919) G18(-10.222,3.919) G20(-11.174,3.919) H5(-2.602,4.569) H6(-3.554,4.569) H8(-4.507,4.569) H10(-5.459,4.569) H11(-6.412,4.569) H13(-7.364,4.569) H15(-8.317,4.569) H17(-9.269,4.569) H18(-10.222,4.569) H20(-11.174,4.569) H59(-36.027,4.145) H60(-36.678,4.145) H61(-37.328,4.145) H62(-37.978,4.183) H63(-38.628,4.183) J1(0,4.973) J2(-0.65,4.973) J3(-1.3,5.011) J4(-1.951,5.011) J5(-2.627,5.22) J6(-3.567,5.22) J8(-4.507,5.22) J10(-5.459,5.22) J11(-6.412,5.22) J13(-7.364,5.22) J15(-8.317,5.22) J17(-9.269,5.22) J18(-10.222,5.22) J20(-11.174,5.22) J21(-12.095,4.986) J59(-36.027,4.971) J60(-36.678,4.971) J61(-37.328,4.971) J62(-37.978,4.933) J63(-38.628,4.933) K1(0,5.722) K2(-0.65,5.722) K3(-1.3,5.684) K4(-1.951,5.684) K59(-36.027,5.644) K60(-36.678,5.644) K61(-37.328,5.644) K62(-37.978,5.682) K63(-38.628,5.682) L1(0,6.471) L2(-0.65,6.471) L3(-1.3,6.51) L4(-1.951,6.51) L5(-2.637,6.338) L6(-3.287,6.338) L7(-3.937,6.338) L8(-4.587,6.338) L59(-36.027,6.469) L60(-36.678,6.469) L61(-37.328,6.469) L62(-37.978,6.431) L63(-38.628,6.431) N1(0,7.221) N2(-0.65,7.221) N3(-1.3,7.183) N4(-1.951,7.183) N5(-2.637,7.29) N6(-3.287,7.29) N7(-3.937,7.29) N8(-4.587,7.29) N59(-36.027,7.142) N60(-36.678,7.142) N61(-37.328,7.142) N62(-37.978,7.181) N63(-38.628,7.181) P1(0,7.97) P2(-0.65,7.97) P3(-1.3,8.008) P4(-1.951,8.008) P59(-36.027,7.968) P60(-36.678,7.968) P61(-37.328,7.968) P62(-37.978,7.93) P63(-38.628,7.93) R5(-2.637,8.243) R6(-3.287,8.243) R7(-3.937,8.243) R8(-4.587,8.243) T1(0,8.719) T2(-0.65,8.719) T3(-1.3,8.681) T4(-1.951,8.681) T59(-36.027,8.641) T60(-36.678,8.641) T61(-37.328,8.641) T62(-37.978,8.679) T63(-38.628,8.679) U1(0,9.469) U2(-0.65,9.469) U3(-1.3,9.507) U4(-1.951,9.507) U5(-2.637,9.195) U6(-3.287,9.195) U7(-3.937,9.195) U8(-4.587,9.195) U59(-36.027,9.467) U60(-36.678,9.467) U61(-37.328,9.467) U62(-37.978,9.428) U63(-38.628,9.428) V1(0,10.218) V2(-0.65,10.218) V3(-1.3,10.18) V4(-1.951,10.18) V5(-2.637,10.148) V6(-3.287,10.148) V7(-3.937,10.148) V8(-4.587,10.148) V59(-36.027,10.14) V60(-36.678,10.14) V61(-37.328,10.14) V62(-37.978,10.178) V63(-38.628,10.178) Y1(0,10.967) Y2(-0.65,10.967) Y3(-1.3,11.005) Y4(-1.951,11.005) Y5(-2.637,11.1) Y6(-3.287,11.1) Y7(-3.937,11.1) Y8(-4.587,11.1) Y59(-36.027,10.965) Y60(-36.678,10.965) Y61(-37.328,10.965) Y62(-37.978,10.927) Y63(-38.628,10.927)
  round 0.33 smd: AK22(-12.655,16.266) AK23(-13.529,16.266) AK25(-14.504,16.266) AK26(-15.456,16.266) AK28(-16.409,16.266) AK29(-17.311,16.266) AK32(-18.824,16.266) AK33(-19.726,16.266) AK35(-20.729,16.266) AK36(-21.58,16.266) AK38(-22.609,16.266) AK40(-24.106,16.266) AK42(-24.944,16.266) AK43(-25.897,16.266) AK45(-26.874,16.266) AK46(-27.776,16.266) AK48(-28.83,16.266) AK49(-29.732,16.266) AK51(-30.735,16.266) AK52(-31.583,16.266) AK54(-32.61,16.266) AK55(-33.562,16.266) AK57(-34.509,16.266) AK58(-35.408,16.266)
BELLW_80148-3221_67P-T
  round 1.092 hole 1.092 unplated: (-0.75,-5.275)
  round 1.6 hole 1.6 unplated: (19.25,-5.275)
  oval 0.305x1.549 smd: 1(0,0) 2(0.25,-7.55) 3(0.5,0) 4(0.75,-7.55) 5(1,0) 6(1.25,-7.55) 7(1.5,0) 8(3.75,-7.55) 9(4,0) 10(4.25,-7.55) 11(4.5,0) 12(4.75,-7.55) 13(5,0) 14(5.25,-7.55) 15(5.5,0) 16(5.75,-7.55) 17(6,0) 18(6.25,-7.55) 19(6.5,0) 20(6.75,-7.55) 21(7,0) 22(7.25,-7.55) 23(7.5,0) 24(7.75,-7.55) 25(8,0) 26(8.25,-7.55) 27(8.5,0) 28(8.75,-7.55) 29(9,0) 30(9.25,-7.55) 31(9.5,0) 32(9.75,-7.55) 33(10,0) 34(10.25,-7.55) 35(10.5,0) 36(10.75,-7.55) 37(11,0) 38(11.25,-7.55) 39(11.5,0) 40(11.75,-7.55) 41(12,0) 42(12.25,-7.55) 43(12.5,0) 44(12.75,-7.55) 45(13,0) 46(13.25,-7.55) 47(13.5,0) 48(13.75,-7.55) 49(14,0) 50(14.25,-7.55) 51(14.5,0) 52(14.75,-7.55) 53(15,0) 54(15.25,-7.55) 55(15.5,0) 56(15.75,-7.55) 57(16,0) 58(16.25,-7.55) 59(16.5,0) 60(16.75,-7.55) 61(17,0) 62(17.25,-7.55) 63(17.5,0) 64(17.75,-7.55) 65(18,0) 66(18.25,-7.55) 67(18.5,0)
  rect 1.194x2.743 smd: 68(-1.1,-0.775) 69(19.6,-0.775)
BELLW_80149-4221_67P-T
  round 1.092 hole 1.092 unplated: (-0.75,-5.275)
  round 1.6 hole 1.6 unplated: (19.25,-5.275)
  oval 0.305x1.549 smd: 1(0,0) 2(0.25,-7.55) 3(0.5,0) 4(0.75,-7.55) 5(1,0) 6(1.25,-7.55) 7(1.5,0) 8(1.75,-7.55) 9(2,0) 10(2.25,-7.55) 11(2.5,0) 12(4.75,-7.55) 13(5,0) 14(5.25,-7.55) 15(5.5,0) 16(5.75,-7.55) 17(6,0) 18(6.25,-7.55) 19(6.5,0) 20(6.75,-7.55) 21(7,0) 22(7.25,-7.55) 23(7.5,0) 24(7.75,-7.55) 25(8,0) 26(8.25,-7.55) 27(8.5,0) 28(8.75,-7.55) 29(9,0) 30(9.25,-7.55) 31(9.5,0) 32(9.75,-7.55) 33(10,0) 34(10.25,-7.55) 35(10.5,0) 36(10.75,-7.55) 37(11,0) 38(11.25,-7.55) 39(11.5,0) 40(11.75,-7.55) 41(12,0) 42(12.25,-7.55) 43(12.5,0) 44(12.75,-7.55) 45(13,0) 46(13.25,-7.55) 47(13.5,0) 48(13.75,-7.55) 49(14,0) 50(14.25,-7.55) 51(14.5,0) 52(14.75,-7.55) 53(15,0) 54(15.25,-7.55) 55(15.5,0) 56(15.75,-7.55) 57(16,0) 58(16.25,-7.55) 59(16.5,0) 60(16.75,-7.55) 61(17,0) 62(17.25,-7.55) 63(17.5,0) 64(17.75,-7.55) 65(18,0) 66(18.25,-7.55) 67(18.5,0)
  rect 1.194x2.743 smd: 68(-1.1,-0.775) 69(19.6,-0.775)
BQ24715URUYR_WQFN28_4X4
  oval 0.889x0.203 smd: 1(0,0) 2(0,-0.4) 3(0,-0.8) 4(0,-1.2) 5(0,-1.6) 6(0,-2) 7(0,-2.4) 15(4.1,-2.4) 16(4.1,-2) 17(4.1,-1.6) 18(4.1,-1.2) 19(4.1,-0.8) 20(4.1,-0.4) 21(4.1,0)
  oval 0.203x0.889 smd: 8(0.85,-3.25) 9(1.25,-3.25) 10(1.65,-3.25) 11(2.05,-3.25) 12(2.45,-3.25) 13(2.85,-3.25) 14(3.25,-3.25) 22(3.25,0.85) 23(2.85,0.85) 24(2.45,0.85) 25(2.05,0.85) 26(1.65,0.85) 27(1.25,0.85) 28(0.85,0.85)
  rect 2.591x2.591 smd: 29(2.05,-1.2)
C-K_26210-8K1A-02_9P-T
  round 1.118 hole 0.711: 1(0,0) 2(-2.5,0) 3(-4.5,0) 4(-7,0) 5(-7.5,-1.5) 6(-5.5,-1.5) 7(-3.5,-1.5) 8(-1.5,-1.5) 9(0.5,-1.5)
  oval 1.549x3.353 hole 0.787x2.591: 10(4.35,-2.43) 11(-11.35,-2.43)
  oval 1.549x2.464 hole 0.787x1.702: 12(-11.35,-9.23) 13(4.35,-9.23)
C_0402
  rect 0.508x0.559 smd: 1(0,0) 2(0.914,0)
C_0603
  rect 0.635x0.889 smd: 1(0,0) 2(1.397,0)
C_0805
  rect 0.813x1.397 smd: 1(0,0) 2(1.702,0)
C_1206
  rect 1.016x1.651 smd: 1(0,0) 2(2.667,0)
C_1808
  rect 1.041x2.311 smd: 1(0,0) 2(4.35,0)
C_APXK6R3ARA221MF451
  oval 3.15x1.6 smd: 1(0,0) 2(5.05,0)
C_B2
  rect 1.346x2.692 smd: 1(0,0) 2(-2.75,0)
C_D
  rect 2.388x2.896 smd: 1(0,0) 2(6.1,0)
C_D2
  rect 2.388x2.794 smd: 1(0,0) 2(6.4,0)
C_D3
  rect 2.388x2.794 smd: 1(0,0) 2(6.4,0)
CD3301RHHR_QFN36_6X6
  oval 0.254x1.194 smd: 1(0,0) 2(0.5,0) 3(1,0) 4(1.5,0) 5(2,0) 6(2.5,0) 7(3,0) 8(3.5,0) 9(4,0) 19(4,5.8) 20(3.5,5.8) 21(3,5.8) 22(2.5,5.8) 23(2,5.8) 24(1.5,5.8) 25(1,5.8) 26(0.5,5.8) 27(0,5.8)
  oval 1.194x0.254 smd: 10(4.9,0.9) 11(4.9,1.4) 12(4.9,1.9) 13(4.9,2.4) 14(4.9,2.9) 15(4.9,3.4) 16(4.9,3.9) 17(4.9,4.4) 18(4.9,4.9) 28(-0.9,4.9) 29(-0.9,4.4) 30(-0.9,3.9) 31(-0.9,3.4) 32(-0.9,2.9) 33(-0.9,2.4) 34(-0.9,1.9) 35(-0.9,1.4) 36(-0.9,0.9)
  rect 4.089x4.089 smd: 37(2,2.9)
CONCR_099BKAC19YBLCNF_19P-T
  round 0.813 hole 0.508: 1(0,0) 2(0.5,1.5) 3(1,0) 4(1.5,1.5) 5(2,0) 6(2.5,1.5) 7(3,0) 8(3.5,1.5) 9(4,0) 10(4.5,1.5) 11(5,0) 12(5.5,1.5) 13(6,0) 14(6.5,1.5) 15(7,0) 16(7.5,1.5) 17(8,0) 18(8.5,1.5) 19(9,0)
  oval 1.397x3.15 hole 0.787x2.54: 20(-2.75,0.9) 21(11.75,0.9)
  oval 1.803x2.794 hole 0.787x1.803: 22(-4.75,-6.08) 23(13.75,-6.08)
CSD97374CQ4M_SON8_3P5X4P5
  oval 0.203x0.889 smd: 1(0,0) 2(0.4,0) 3(0.8,0) 6(0.8,3.5) 7(0.4,3.5) 8(0,3.5)
  custom 0.225x0.225 smd: 4(2.2,0.262) 5(2.2,3.238)
  rect 4.039x2.21 smd: 9(1.6,1.75)
DDTA114EUA-7-F_SOT323-3
  oval 0.813x0.914 smd: 1(0,0) 2(0.65,1.6) 3(-0.65,1.6)
DEREN_40-42251-01001RHF_10P-T
  oval 0.838x2.21 smd: 1(0,0.1) 2(1.5,0.1) 3(3,0.1) 4(4.5,0.1) 5(6,0.1) 6(7.5,0.1) 7(9,0.1) 8(10.5,0.1) 9(12,0.1) 10(13.5,0.1)
  custom 0.75x0.75 smd: 11(-3.4,-3.15) 12(16.9,-3.15)
DMN65D8LDW-7_SOT363-6
  oval 0.432x0.61 smd: 1(0,0) 2(0.65,0) 3(1.3,0) 4(1.3,1.9) 5(0.65,1.9) 6(0,1.9)
DMN65D8LW-7_SOT323-3
  oval 0.711x0.889 smd: 1(0,0) 2(-0.65,-1.9) 3(0.65,-1.9)
DMN66D0LDW-7_SOT363-6
  oval 0.432x0.61 smd: 1(0,0) 2(0.65,0) 3(1.3,0) 4(1.3,1.9) 5(0.65,1.9) 6(0,1.9)
E-T_6700K-Y20N-00L_20P
  oval 0.61x1.499 smd: 1(0,0) 2(-0.5,-2.8) 3(-1,0) 4(-1.5,-2.8) 5(-2,0) 6(-2.5,-2.8) 7(-3,0) 8(-3.5,-2.8) 9(-4,0) 10(-4.5,-2.8) 11(-5,0) 12(-5.5,-2.8) 13(-6,0) 14(-6.5,-2.8) 15(-7,0) 16(-7.5,-2.8) 17(-8,0) 18(-8.5,-2.8) 19(-9,0) 20(-9.5,-2.8)
  rect 0.787x1.499 smd: 21(1,0) 22(1,-2.8) 23(-10.5,0) 24(-10.5,-2.8)
E-T_6705K-Y10N-00L_10P-T
  oval 0.305x1.092 smd: 1(0,0) 2(0.5,0) 3(1,0) 4(1.5,0) 5(2,0) 6(2.5,0) 7(3,0) 8(3.5,0) 9(4,0) 10(4.5,0)
  rect 0.991x2.007 smd: 11(-2.1,-3.15) 12(6.6,-3.15)
E-T_6705K-Y16N-00L_16P
  oval 0.305x1.092 smd: 1(0,0) 2(0.5,0) 3(1,0) 4(1.5,0) 5(2,0) 6(2.5,0) 7(3,0) 8(3.5,0) 9(4,0) 10(4.5,0) 11(5,0) 12(5.5,0) 13(6,0) 14(6.5,0) 15(7,0) 16(7.5,0)
  rect 0.991x2.007 smd: 17(-2.1,-3.15) 18(9.6,-3.15)
E-T_6705K-Y20N-00L_20P
  oval 0.305x1.092 smd: 1(0,0) 2(-0.5,0) 3(-1,0) 4(-1.5,0) 5(-2,0) 6(-2.5,0) 7(-3,0) 8(-3.5,0) 9(-4,0) 10(-4.5,0) 11(-5,0) 12(-5.5,0) 13(-6,0) 14(-6.5,0) 15(-7,0) 16(-7.5,0) 17(-8,0) 18(-8.5,0) 19(-9,0) 20(-9.5,0)
  rect 0.991x2.007 smd: 21(2.1,-3.15) 22(-11.6,-3.15)
ECE5048-LZY_DQFN132_11X11
  oval 0.279x0.737 smd: A1(0,0) A2(0.5,0) A3(1,0) A4(1.5,0) A5(2,0) A6(2.5,0) A7(3,0) A8(3.5,0) A9(4,0) A10(4.5,0) A11(5,0) A12(5.5,0) A13(6,0) A14(6.5,0) A15(7,0) A16(7.5,0) A33(7.5,10.9) A34(7,10.9) A35(6.5,10.9) A36(6,10.9) A37(5.5,10.9) A38(5,10.9) A39(4.5,10.9) A40(4,10.9) A41(3.5,10.9) A42(3,10.9) A43(2.5,10.9) A44(2,10.9) A45(1.5,10.9) A46(1,10.9) A47(0.5,10.9) A48(0,10.9)
  oval 0.737x0.279 smd: A17(9.2,1.7) A18(9.2,2.2) A19(9.2,2.7) A20(9.2,3.2) A21(9.2,3.7) A22(9.2,4.2) A23(9.2,4.7) A24(9.2,5.2) A25(9.2,5.7) A26(9.2,6.2) A27(9.2,6.7) A28(9.2,7.2) A29(9.2,7.7) A30(9.2,8.2) A31(9.2,8.7) A32(9.2,9.2) A49(-1.7,9.2) A50(-1.7,8.7) A51(-1.7,8.2) A52(-1.7,7.7) A53(-1.7,7.2) A54(-1.7,6.7) A55(-1.7,6.2) A56(-1.7,5.7) A57(-1.7,5.2) A58(-1.7,4.7) A59(-1.7,4.2) A60(-1.7,3.7) A61(-1.7,3.2) A62(-1.7,2.7) A63(-1.7,2.2) A64(-1.7,1.7)
  oval 0.318x0.61 smd: B1(-0.25,0.855) B2(0.25,0.855) B3(0.75,0.855) B4(1.25,0.855) B5(1.75,0.855) B6(2.25,0.855) B7(2.75,0.855) B8(3.25,0.855) B9(3.75,0.855) B10(4.25,0.855) B11(4.75,0.855) B12(5.25,0.855) B13(5.75,0.855) B14(6.25,0.855) B15(6.75,0.855) B16(7.25,0.855) B17(7.75,0.855) B35(7.75,10.045) B36(7.25,10.045) B37(6.75,10.045) B38(6.25,10.045) B39(5.75,10.045) B40(5.25,10.045) B41(4.75,10.045) B42(4.25,10.045) B43(3.75,10.045) B44(3.25,10.045) B45(2.75,10.045) B46(2.25,10.045) B47(1.75,10.045) B48(1.25,10.045) B49(0.75,10.045) B50(0.25,10.045) B51(-0.25,10.045)
  oval 0.61x0.318 smd: B18(8.345,1.45) B19(8.345,1.95) B20(8.345,2.45) B21(8.345,2.95) B22(8.345,3.45) B23(8.345,3.95) B24(8.345,4.45) B25(8.345,4.95) B26(8.345,5.45) B27(8.345,5.95) B28(8.345,6.45) B29(8.345,6.95) B30(8.345,7.45) B31(8.345,7.95) B32(8.345,8.45) B33(8.345,8.95) B34(8.345,9.45) B52(-0.845,9.45) B53(-0.845,8.95) B54(-0.845,8.45) B55(-0.845,7.95) B56(-0.845,7.45) B57(-0.845,6.95) B58(-0.845,6.45) B59(-0.845,5.95) B60(-0.845,5.45) B61(-0.845,4.95) B62(-0.845,4.45) B63(-0.845,3.95) B64(-0.845,3.45) B65(-0.845,2.95) B66(-0.845,2.45) B67(-0.845,1.95) B68(-0.845,1.45)
  rect 5.105x5.105 smd: C1(3.75,5.45)
